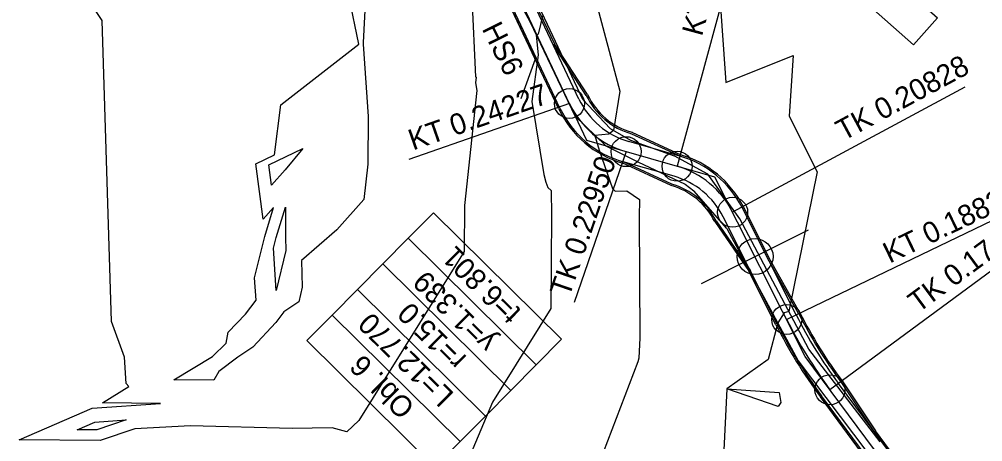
# Model space of a CAD drawing. Extents: x -549394 to -546608, y -1037055 to -1033629.
# Drawn here: x -547910.2 to -547749.6, y -1034785.5 to -1034715 of the extents above; entities that cross this region are included whole.
import ezdxf

# ---------------------------------------------------------------- set-up
doc = ezdxf.new("R2010")
doc.units = 0
for name, color, linetype in [('03_PC_OBJEKTY_STAV', 7, 'Continuous'), ('hlavni_vrst', 7, 'Continuous'), ('hrana_L', 7, 'Continuous'), ('norm_vrst', 7, 'Continuous'), ('POLYGONY_SITUACE_PO', 7, 'Continuous'), ('u_sirka_1_0m', 7, 'Continuous'), ('x_navrh_C21', 7, 'Continuous'), ('x_osa_C21', 7, 'Continuous'), ('x_popis_C21', 7, 'Continuous'), ('x_popis_oblouky_C21', 7, 'Continuous'), ('x_popis_pricne_rezy_C21', 7, 'Continuous'), ('x_popis_velky_C21', 7, 'Continuous')]:
    doc.layers.add(name, color=color, linetype=linetype)

msp = doc.modelspace()

# ---------------------------------------------------------------- linework, layer by layer
at = {"layer": '03_PC_OBJEKTY_STAV'}
msp.add_lwpolyline([(-547835.16, -1034710.23), (-547828.5, -1034712.62), (-547824.24, -1034721.67), (-547826.63, -1034728.32)], dxfattribs=at)
at = {"layer": 'hlavni_vrst'}
for p, q in [((-547822.95, -1034714.28), (-547823.74, -1034717.53)), ((-547823.74, -1034717.53), (-547824.08, -1034717.68)), ((-547824.08, -1034717.68), (-547823.71, -1034721)), ((-547823.71, -1034721), (-547824.8, -1034728.76)), ((-547824.8, -1034728.76), (-547822.8, -1034740.91)), ((-547822.8, -1034740.91), (-547822.44, -1034742.18)), ((-547822.44, -1034742.18), (-547822.12, -1034743.12)), ((-547822.12, -1034743.12), (-547821.56, -1034743.61)), ((-547821.56, -1034743.61), (-547821.51, -1034747.7)), ((-547821.51, -1034747.7), (-547821.6, -1034763.26)), ((-547821.6, -1034763.26), (-547831.37, -1034778.88)), ((-547831.37, -1034778.88), (-547838.89, -1034796.79))]:
    msp.add_line(p, q, dxfattribs=at)
at = {"layer": 'hrana_L'}
for p, q in [((-547834.9, -1034696.97), (-547825.09, -1034715.55)), ((-547816.3, -1034728.43), (-547823.55, -1034712.99)), ((-547825.09, -1034715.55), (-547817.65, -1034731.14)), ((-547816.3, -1034728.43), (-547811.71, -1034733.28)), ((-547817.65, -1034731.14), (-547812.44, -1034736.16)), ((-547811.71, -1034733.28), (-547808.35, -1034735.19)), ((-547812.44, -1034736.16), (-547807.11, -1034738.8)), ((-547808.35, -1034735.19), (-547801.05, -1034737.8)), ((-547795.47, -1034740.88), (-547801.05, -1034737.8)), ((-547807.11, -1034738.8), (-547799.21, -1034742.53)), ((-547790.15, -1034748.33), (-547795.47, -1034740.88)), ((-547799.21, -1034742.53), (-547797.77, -1034743.66)), ((-547792.27, -1034749.93), (-547797.77, -1034743.66)), ((-547778.63, -1034770.04), (-547790.15, -1034748.33)), ((-547792.27, -1034749.93), (-547780.43, -1034771.99)), ((-547766.75, -1034785.52), (-547778.63, -1034770.04)), ((-547780.43, -1034771.99), (-547768.8, -1034787.38))]:
    msp.add_line(p, q, dxfattribs=at)
at = {"layer": 'norm_vrst'}
for p, q in [((-547896.4, -1034715.27), (-547904.3, -1034703.2)), ((-547793.92, -1034704.37), (-547792.45, -1034725.58)), ((-547852.23, -1034705.46), (-547852.92, -1034718.94)), ((-547853.65, -1034719.19), (-547856.25, -1034706.52)), ((-547834.94, -1034708.62), (-547834.18, -1034724.62)), ((-547815.21, -1034707.93), (-547810.13, -1034727.01)), ((-547894.84, -1034765.45), (-547896.4, -1034715.27)), ((-547852.92, -1034718.94), (-547852.89, -1034719.21)), ((-547866.63, -1034729.29), (-547853.65, -1034719.19)), ((-547852.89, -1034719.21), (-547852.08, -1034731.24)), ((-547792.45, -1034725.58), (-547781.26, -1034721.09)), ((-547781.26, -1034721.09), (-547781.91, -1034731.18)), ((-547834.07, -1034724.69), (-547834.2, -1034725.62)), ((-547834.18, -1034724.62), (-547834.07, -1034724.69)), ((-547833.98, -1034726.93), (-547836, -1034746.08)), ((-547834.2, -1034725.62), (-547833.98, -1034726.93)), ((-547810.13, -1034727.01), (-547811.18, -1034733.58)), ((-547810.13, -1034727.01), (-547810.13, -1034727.01)), ((-547810.13, -1034727.01), (-547810.13, -1034727.01)), ((-547810.13, -1034727.01), (-547810.13, -1034727.01)), ((-547810.13, -1034727.01), (-547810.13, -1034727.01)), ((-547867.66, -1034737.67), (-547866.63, -1034729.29)), ((-547852.08, -1034731.24), (-547852.13, -1034739.18)), ((-547781.91, -1034731.18), (-547777.22, -1034740.51)), ((-547811.94, -1034734.19), (-547814.27, -1034734.4)), ((-547814.27, -1034734.4), (-547813.59, -1034736.85)), ((-547811.18, -1034733.58), (-547811.94, -1034734.19)), ((-547868.65, -1034739.34), (-547862.94, -1034736.6)), ((-547862.94, -1034736.6), (-547865.91, -1034740.13)), ((-547870.8, -1034739.17), (-547867.66, -1034737.67)), ((-547813.59, -1034736.85), (-547811.37, -1034743.27)), ((-547869.57, -1034748.4), (-547870.8, -1034739.17)), ((-547868.2, -1034742.69), (-547868.65, -1034739.34)), ((-547852.13, -1034739.18), (-547852.8, -1034745.12)), ((-547865.91, -1034740.13), (-547868.2, -1034742.69)), ((-547777.22, -1034740.51), (-547781.95, -1034763.78)), ((-547811.37, -1034743.27), (-547810.88, -1034743.7)), ((-547810.88, -1034743.7), (-547808.95, -1034743.64)), ((-547808.95, -1034743.64), (-547806.87, -1034745.11)), ((-547867.4, -1034751.41), (-547865.85, -1034746.4)), ((-547865.85, -1034746.4), (-547865.84, -1034751.37)), ((-547852.8, -1034745.12), (-547857.31, -1034750.17)), ((-547836, -1034746.08), (-547836.05, -1034753.79)), ((-547806.87, -1034745.11), (-547806.89, -1034747.97)), ((-547867.82, -1034746.44), (-547869.57, -1034748.4)), ((-547869.31, -1034751.27), (-547867.82, -1034746.44)), ((-547806.89, -1034747.97), (-547806.79, -1034768.14)), ((-547857.31, -1034750.17), (-547863.18, -1034755.25)), ((-547871.01, -1034758.14), (-547869.31, -1034751.27)), ((-547867.84, -1034753.19), (-547867.4, -1034751.41)), ((-547865.84, -1034751.37), (-547865.78, -1034753.61)), ((-547867.38, -1034760.26), (-547867.84, -1034753.19)), ((-547865.78, -1034753.61), (-547867.38, -1034760.26)), ((-547836.05, -1034753.79), (-547853.64, -1034781.94)), ((-547863.18, -1034755.25), (-547863.05, -1034759.74)), ((-547870.76, -1034761.88), (-547871.01, -1034758.14)), ((-547863.05, -1034759.74), (-547863.63, -1034762.16)), ((-547872.52, -1034764.2), (-547870.76, -1034761.88)), ((-547863.63, -1034762.16), (-547866.1, -1034763.84)), ((-547866.1, -1034763.84), (-547867.47, -1034765.63)), ((-547782.72, -1034764.01), (-547783.81, -1034765.69)), ((-547781.95, -1034763.78), (-547782.72, -1034764.01)), ((-547892.68, -1034771.41), (-547894.84, -1034765.45)), ((-547875.38, -1034767.23), (-547872.52, -1034764.2)), ((-547867.47, -1034765.63), (-547871.28, -1034769.73)), ((-547783.81, -1034765.69), (-547785.4, -1034771.76)), ((-547875.72, -1034769.06), (-547875.38, -1034767.23)), ((-547806.79, -1034768.14), (-547806.98, -1034771.55)), ((-547878.03, -1034771.25), (-547875.72, -1034769.06)), ((-547871.28, -1034769.73), (-547873.77, -1034771.38)), ((-547892.39, -1034775.78), (-547892.68, -1034771.41)), ((-547884.43, -1034775.15), (-547878.03, -1034771.25)), ((-547873.77, -1034771.38), (-547876.97, -1034773.79)), ((-547806.98, -1034771.55), (-547807.11, -1034772.14)), ((-547785.4, -1034771.76), (-547792.3, -1034776.68)), ((-547807.11, -1034772.14), (-547813.87, -1034789.74)), ((-547877.8, -1034775.24), (-547884.43, -1034775.15)), ((-547876.97, -1034773.79), (-547877.8, -1034775.24)), ((-547896.37, -1034779), (-547891.93, -1034776.3)), ((-547891.93, -1034776.3), (-547892.39, -1034775.78)), ((-547792.3, -1034776.68), (-547793.96, -1034809.67)), ((-547783.75, -1034779.6), (-547792.3, -1034776.68)), ((-547792.3, -1034776.68), (-547792.3, -1034776.68)), ((-547792.3, -1034776.68), (-547783.56, -1034777.29)), ((-547792.3, -1034776.68), (-547792.3, -1034776.68)), ((-547783.56, -1034777.29), (-547783.3, -1034778.97)), ((-547910.22, -1034785.17), (-547898.09, -1034779.92)), ((-547898.09, -1034779.92), (-547886.67, -1034779.14)), ((-547886.67, -1034779.14), (-547896.37, -1034779)), ((-547783.3, -1034778.97), (-547783.75, -1034779.6)), ((-547900.58, -1034783.49), (-547897.64, -1034782.22)), ((-547897.64, -1034782.22), (-547892.41, -1034781.86)), ((-547892.41, -1034781.86), (-547897.31, -1034783.52)), ((-547890.93, -1034783.34), (-547896.73, -1034785.31)), ((-547881.68, -1034782.83), (-547890.93, -1034783.34)), ((-547864.71, -1034783.27), (-547881.68, -1034782.83)), ((-547858.09, -1034783.17), (-547864.71, -1034783.27)), ((-547855.65, -1034783.84), (-547858.09, -1034783.17)), ((-547853.64, -1034781.94), (-547855.65, -1034783.84)), ((-547897.31, -1034783.52), (-547900.58, -1034783.49)), ((-547896.73, -1034785.31), (-547910.22, -1034785.17))]:
    msp.add_line(p, q, dxfattribs=at)
at = {"layer": 'POLYGONY_SITUACE_PO'}
for centre in [(-547818.52, -1034729.09), (-547809.08, -1034737.12), (-547800.59, -1034739.55), (-547791.32, -1034747.23), (-547782.31, -1034765.11), (-547775.1, -1034776.82)]:
    msp.add_circle(centre, 2.5, dxfattribs=at)
at = {"layer": 'u_sirka_1_0m'}
msp.add_circle((-547787.59, -1034754.62), 3, dxfattribs=at)
at = {"layer": 'x_navrh_C21'}
for p, q in [((-547820.98, -1034719.18), (-547829.31, -1034701.53)), ((-547820.33, -1034729.95), (-547828.66, -1034712.28)), ((-547815.49, -1034727.61), (-547821.02, -1034719.12)), ((-547815.71, -1034727.73), (-547821.24, -1034719.24)), ((-547808.19, -1034734.13), (-547800.03, -1034737.89)), ((-547808.1, -1034733.89), (-547799.95, -1034737.66)), ((-547801.57, -1034742.77), (-547809.72, -1034739.01)), ((-547801.48, -1034742.54), (-547809.64, -1034738.77)), ((-547785.03, -1034755.27), (-547789.53, -1034746.33)), ((-547794.31, -1034748.79), (-547788.57, -1034757.13)), ((-547794.09, -1034748.66), (-547788.35, -1034757)), ((-547780.32, -1034764.09), (-547785.26, -1034755.37)), ((-547780.1, -1034763.98), (-547785.04, -1034755.25)), ((-547784.1, -1034766.01), (-547788.6, -1034757.07)), ((-547773.29, -1034775.49), (-547767.72, -1034783.82)), ((-547773.09, -1034775.35), (-547767.51, -1034783.68)), ((-547757.06, -1034804.47), (-547776.7, -1034778.01)), ((-547759.81, -1034794.05), (-547767.53, -1034783.66))]:
    msp.add_line(p, q, dxfattribs=at)
for centre, radius, start, end in [((-547804.95, -1034722.7), 11.88, 205.0806, 254.2059), ((-547804.95, -1034722.7), 11.63, 204.9954, 254.3023), ((-547804.95, -1034722.7), 17, 205.2434, 253.9549), ((-547804.72, -1034753.97), 17, 26.7249, 73.9549), ((-547804.72, -1034753.97), 11.63, 26.4769, 74.3023), ((-547804.72, -1034753.97), 11.88, 26.5622, 74.2059), ((-547710.86, -1034729.13), 77.51, 206.7114, 216.5983), ((-547710.86, -1034729.13), 77.76, 206.7159, 216.5938), ((-547710.86, -1034729.13), 82, 206.7249, 216.5847)]:
    msp.add_arc(centre, radius, start, end, dxfattribs=at)
at = {"layer": 'x_osa_C21'}
for points in [[(-547815.62, -1034735.25), (-547833.77, -1034696.75), (-547865.08, -1034658.69)], [(-547794.27, -1034741.36), (-547815.62, -1034735.25)], [(-547716.54, -1034842.38), (-547750.35, -1034810.16), (-547779.21, -1034771.27), (-547794.27, -1034741.36)]]:
    msp.add_lwpolyline(points, dxfattribs=at)
for centre, radius, start, end in [((-547804.95, -1034722.7), 15, 205.2434, 254.022), ((-547804.72, -1034753.97), 15, 26.7249, 74.022), ((-547710.86, -1034729.13), 80, 206.7249, 216.5847)]:
    msp.add_arc(centre, radius, start, end, dxfattribs=at)
at = {"layer": 'x_popis_oblouky_C21'}
for points in [[(-547779.66, -1034694.93), (-547757.2, -1034714.82), (-547761.18, -1034719.31), (-547783.64, -1034699.42)], [(-547824.07, -1034772.67), (-547845.4, -1034751.57), (-547841.18, -1034747.3), (-547819.85, -1034768.4)], [(-547828.29, -1034776.93), (-547849.62, -1034755.83), (-547845.4, -1034751.57), (-547824.07, -1034772.67)], [(-547832.51, -1034781.2), (-547853.84, -1034760.1), (-547849.62, -1034755.83), (-547828.29, -1034776.93)], [(-547836.73, -1034785.46), (-547858.06, -1034764.37), (-547853.84, -1034760.1), (-547832.51, -1034781.2)], [(-547840.95, -1034789.73), (-547862.28, -1034768.63), (-547858.06, -1034764.37), (-547836.73, -1034785.46)]]:
    msp.add_lwpolyline(points, close=True, dxfattribs=at)
for points in [[(-547789.06, -1034697.13), (-547800.59, -1034739.55)], [(-547752.63, -1034726.36), (-547791.32, -1034747.23)], [(-547818.52, -1034729.09), (-547845.29, -1034738.43)], [(-547809.08, -1034737.12), (-547817.73, -1034762.27)], [(-547745.04, -1034747.15), (-547782.31, -1034765.11)], [(-547741.8, -1034752.26), (-547775.1, -1034776.82)]]:
    msp.add_lwpolyline(points, dxfattribs=at)
at = {"layer": 'x_popis_pricne_rezy_C21'}
msp.add_lwpolyline([(-547796.52, -1034759.12), (-547787.59, -1034754.62), (-547778.66, -1034750.13)], dxfattribs=at)
at = {"layer": 'x_popis_velky_C21'}
for p, q in [((-547816.94, -1034728.35), (-547829.53, -1034701.63)), ((-547820.1, -1034729.84), (-547832.7, -1034703.12)), ((-547800.1, -1034737.87), (-547808.6, -1034735.44)), ((-547801.07, -1034741.23), (-547809.56, -1034738.8)), ((-547783.88, -1034765.9), (-547792.88, -1034748.01)), ((-547780.75, -1034764.32), (-547789.76, -1034746.44)), ((-547754.05, -1034802.23), (-547773.69, -1034775.77)), ((-547756.86, -1034804.32), (-547776.5, -1034777.86))]:
    msp.add_line(p, q, dxfattribs=at)
for centre, radius, start, end in [((-547804.95, -1034722.7), 13.25, 205.2434, 254.022), ((-547804.95, -1034722.7), 16.75, 205.2434, 254.022), ((-547804.72, -1034753.97), 16.75, 26.7249, 74.022), ((-547804.72, -1034753.97), 13.25, 26.7249, 74.022), ((-547710.86, -1034729.13), 78.25, 206.7249, 216.5847), ((-547710.86, -1034729.13), 81.75, 206.7249, 216.5847)]:
    msp.add_arc(centre, radius, start, end, dxfattribs=at)

# ---------------------------------------------------------------- texts
at = {"layer": 'x_popis_C21'}
msp.add_text('HS6', height=3.5, rotation=296.4111, dxfattribs=at).set_placement((-547833.19, -1034716.61))
at = {"layer": 'x_popis_oblouky_C21'}
for s, rotation, p in [('KT 0.22067', 74.8025, (-547796.45, -1034718.01)), ('TK 0.20828', 28.3427, (-547772.89, -1034735.4)), ('KT 0.24227', 19.2364, (-547844.61, -1034736.94)), ('TK 0.22950', 71.0182, (-547818.56, -1034761.51)), ('KT 0.18826', 25.7371, (-547765.17, -1034755.81)), ('TK 0.17449', 36.4144, (-547760.4, -1034764.1)), ('t=6.801', 135.3325, (-547826.36, -1034763.67)), ('y=1.339', 135.3325, (-547830.49, -1034768.51)), ('r=15.0', 135.3325, (-547835.48, -1034771.4)), ('L=12.770', 135.3325, (-547837.59, -1034777.51)), ('Obl. 6', 135.3325, (-547844.09, -1034779.52))]:
    msp.add_text(s, height=3.5, rotation=rotation, dxfattribs=at).set_placement(p)

doc.saveas('drawing.dxf')
